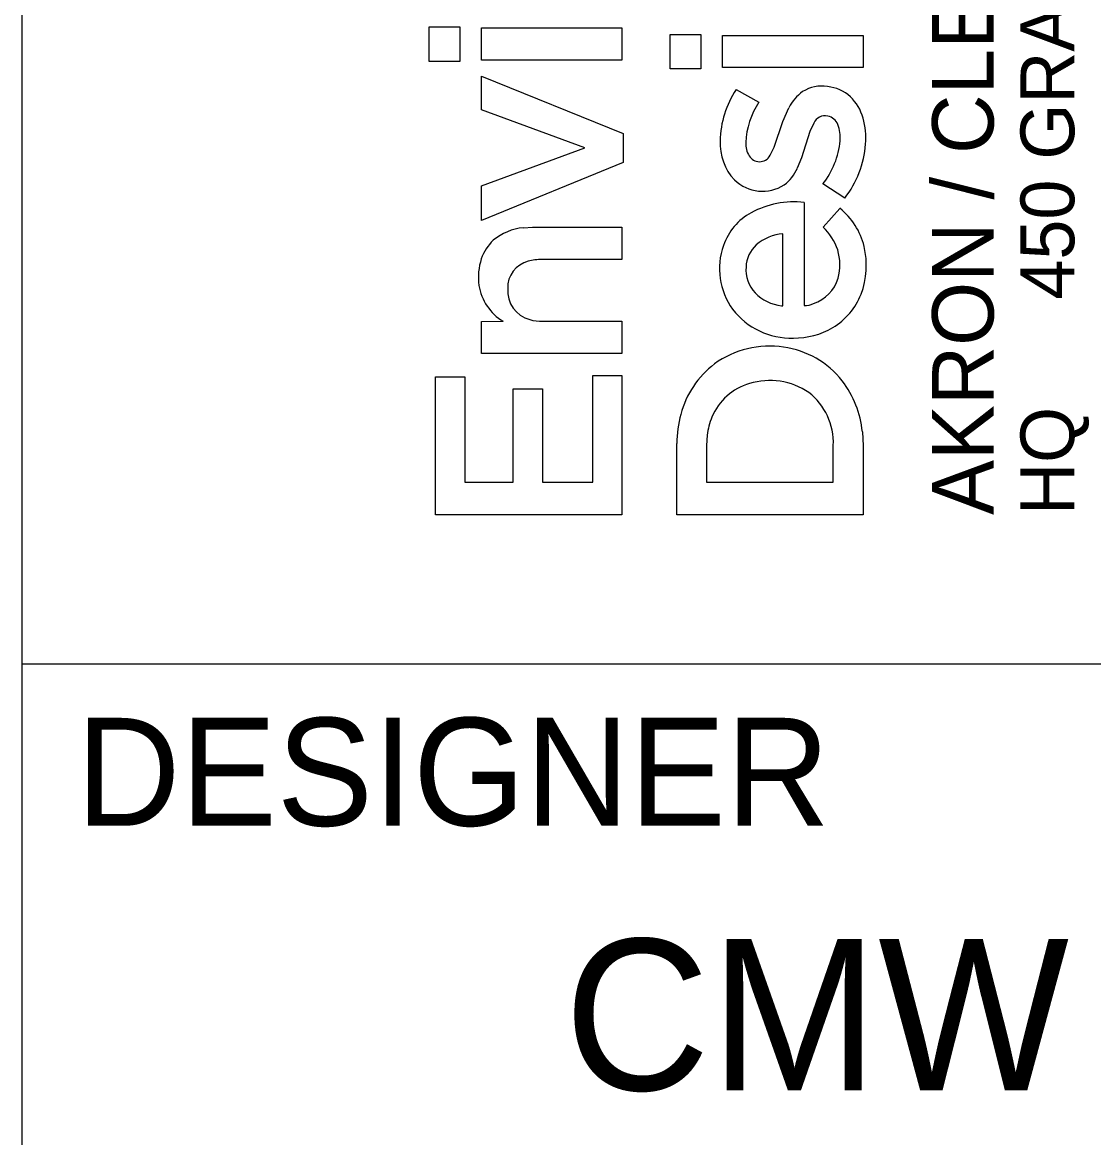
# Model space of a CAD drawing. Extents: x 0 to 1700, y 0 to 1100.
# Drawn here: x 1600 to 1649.6, y 103 to 154.7 of the extents above; entities that cross this region are included whole.
import ezdxf

# ---------------------------------------------------------------- set-up
doc = ezdxf.new("R2010")
doc.units = 0
doc.layers.add('SH_Border', color=7, linetype='Continuous')
doc.layers.add('SH_Data', color=7, linetype='Continuous')

msp = doc.modelspace()

# ---------------------------------------------------------------- linework, layer by layer
at = {"layer": 'SH_Border'}
for p, q in [((1600, 25), (1600, 1075)), ((1600, 125), (1675, 125))]:
    msp.add_line(p, q, dxfattribs=at)
at = {"layer": 'SH_Data'}
for p, q in [((1618.853, 152.909), (1618.853, 154.513)), ((1618.853, 154.513), (1620.272, 154.513)), ((1620.272, 154.513), (1620.272, 152.909)), ((1621.271, 152.971), (1621.271, 154.464)), ((1621.271, 154.464), (1627.786, 154.464)), ((1627.786, 154.464), (1627.786, 152.971)), ((1630.025, 152.555), (1630.025, 154.159)), ((1630.025, 154.159), (1631.444, 154.159)), ((1631.444, 154.159), (1631.444, 152.555)), ((1632.444, 152.617), (1632.444, 154.11)), ((1632.444, 154.11), (1638.958, 154.11)), ((1638.958, 154.11), (1638.958, 152.617)), ((1627.786, 152.971), (1621.271, 152.971)), ((1620.272, 152.909), (1618.853, 152.909)), ((1631.444, 152.555), (1630.025, 152.555)), ((1638.958, 152.617), (1632.444, 152.617)), ((1621.271, 150.663), (1621.271, 152.23)), ((1621.271, 152.23), (1627.835, 149.565)), ((1633.076, 151.603), (1634.134, 151.013)), ((1626.058, 148.899), (1621.271, 150.663)), ((1635.242, 150.129), (1635.518, 150.763)), ((1634.837, 148.934), (1635.242, 150.129)), ((1636.671, 150.05), (1636.492, 149.665)), ((1627.835, 149.565), (1627.835, 148.22)), ((1636.492, 149.665), (1636.106, 148.441)), ((1621.271, 147.147), (1626.058, 148.899)), ((1634.649, 148.558), (1634.837, 148.934)), ((1636.106, 148.441), (1635.911, 147.96)), ((1627.835, 148.22), (1621.271, 145.543)), ((1621.271, 145.543), (1621.271, 147.147)), ((1638.107, 146.571), (1637.099, 147.235)), ((1636.226, 146.373), (1636.232, 141.597)), ((1637.114, 145.232), (1637.884, 146.1)), ((1623.219, 145.199), (1623.645, 145.222)), ((1623.645, 145.222), (1627.785, 145.222)), ((1627.785, 145.222), (1627.786, 143.732)), ((1635.245, 141.591), (1635.245, 144.917)), ((1627.786, 143.732), (1624.07, 143.729)), ((1635.18, 141.583), (1635.245, 141.591)), ((1621.271, 140.864), (1622.276, 140.866)), ((1621.271, 139.373), (1621.271, 140.864)), ((1624.111, 140.866), (1627.785, 140.866)), ((1627.785, 140.866), (1627.786, 139.378)), ((1627.786, 139.378), (1621.271, 139.373)), ((1619.149, 131.896), (1619.149, 138.299)), ((1619.149, 138.299), (1620.506, 138.299)), ((1620.506, 138.299), (1620.506, 133.413)), ((1626.428, 133.413), (1626.428, 138.361)), ((1626.428, 138.361), (1627.786, 138.361)), ((1627.786, 138.361), (1627.786, 131.896)), ((1622.752, 133.413), (1622.752, 137.744)), ((1622.752, 137.744), (1624.109, 137.744)), ((1624.109, 137.744), (1624.109, 133.413)), ((1631.733, 135.589), (1631.703, 135.115)), ((1638.924, 135.748), (1638.958, 135.105)), ((1630.322, 131.899), (1630.322, 135.2)), ((1631.703, 135.115), (1631.703, 133.419)), ((1637.575, 133.417), (1637.576, 135.12)), ((1638.958, 135.105), (1638.958, 131.9)), ((1620.506, 133.413), (1622.752, 133.413)), ((1624.109, 133.413), (1626.428, 133.413)), ((1631.703, 133.419), (1637.575, 133.417)), ((1627.786, 131.896), (1619.149, 131.896)), ((1638.958, 131.9), (1630.322, 131.899))]:
    msp.add_line(p, q, dxfattribs=at)
for points in [[(1618.853, 152.909), (1618.853, 154.513), (1620.272, 154.513), (1620.272, 152.909)], [(1621.271, 152.971), (1621.271, 154.464), (1627.786, 154.464), (1627.786, 152.971)], [(1630.025, 152.555), (1630.025, 154.159), (1631.444, 154.159), (1631.444, 152.555)], [(1632.444, 152.617), (1632.444, 154.11), (1638.958, 154.11), (1638.958, 152.617)], [(1621.271, 145.543), (1621.271, 147.147), (1626.058, 148.899), (1621.271, 150.663), (1621.271, 152.23), (1627.835, 149.565), (1627.835, 148.22)], [(1619.149, 131.896), (1619.149, 138.299), (1620.506, 138.299), (1620.506, 133.413), (1622.752, 133.413), (1622.752, 137.744), (1624.109, 137.744), (1624.109, 133.413), (1626.428, 133.413), (1626.428, 138.361), (1627.786, 138.361), (1627.786, 131.896)]]:
    msp.add_lwpolyline(points, close=True, dxfattribs=at)
for points in [[(1633.076, 151.603), (1634.134, 151.013)], [(1634.649, 148.558), (1634.837, 148.934), (1635.242, 150.129), (1635.518, 150.763)], [(1636.671, 150.05), (1636.492, 149.665), (1636.106, 148.441), (1635.911, 147.96)], [(1638.107, 146.571), (1637.099, 147.235)], [(1636.226, 146.373), (1636.232, 141.597)], [(1637.114, 145.232), (1637.884, 146.1)], [(1623.219, 145.199), (1623.645, 145.222), (1627.785, 145.222), (1627.786, 143.732), (1624.07, 143.729)], [(1635.18, 141.583), (1635.245, 141.591), (1635.245, 144.917)], [(1621.271, 139.373), (1621.271, 140.864), (1622.276, 140.866)], [(1624.111, 140.866), (1627.785, 140.866), (1627.786, 139.378), (1621.271, 139.373)], [(1638.924, 135.748), (1638.958, 135.105), (1638.958, 131.9), (1630.322, 131.899)], [(1631.733, 135.589), (1631.703, 135.115), (1631.703, 133.419), (1637.575, 133.417), (1637.576, 135.12)], [(1630.322, 131.899), (1630.322, 135.2)]]:
    msp.add_lwpolyline(points, dxfattribs=at)
for centre, radius, start, end in [((1636.818, 149.129), 4.486, 146.531, 178.7571), ((1636.818, 149.129), 4.486, 146.531, 178.7571), ((1637.33, 149.856), 2.026, 125.5118, 153.4159), ((1637.33, 149.856), 2.026, 125.5118, 153.4159), ((1637.03, 150.13), 1.632, 80.1719, 122.5197), ((1637.03, 150.13), 1.632, 80.1719, 122.5197), ((1637.139, 149.912), 1.834, 47.7934, 84.6892), ((1637.139, 149.912), 1.834, 47.7934, 84.6892), ((1637.259, 148.945), 3.747, 146.5112, 176.9101), ((1637.259, 148.945), 3.747, 146.5112, 176.9101), ((1636.894, 149.73), 2.134, 14.9966, 46.2063), ((1636.894, 149.73), 2.134, 14.9966, 46.2063), ((1637.192, 149.815), 0.571, 76.6609, 155.7053), ((1637.192, 149.815), 0.571, 76.6609, 155.7053), ((1637.199, 149.756), 0.628, 21.5098, 78.5262), ((1637.199, 149.756), 0.628, 21.5098, 78.5262), ((1636.296, 149.383), 1.605, 354.5726, 22.068), ((1636.296, 149.383), 1.605, 354.5726, 22.068), ((1635.522, 149.337), 3.561, 355.8306, 15.3914), ((1635.522, 149.337), 3.561, 355.8306, 15.3914), ((1634.833, 149.119), 2.503, 177.5366, 222.7932), ((1634.833, 149.119), 2.503, 177.5366, 222.7932), ((1634.655, 149.117), 1.138, 178.4747, 211.0868), ((1634.655, 149.117), 1.138, 178.4747, 211.0868), ((1634.124, 149.575), 3.785, 321.811, 354.7969), ((1634.124, 149.575), 3.785, 321.811, 354.7969), ((1634.476, 149.41), 4.609, 321.9777, 355.8738), ((1634.476, 149.41), 4.609, 321.9777, 355.8738), ((1634.166, 148.835), 0.574, 212.2368, 268.3777), ((1634.166, 148.835), 0.574, 212.2368, 268.3777), ((1634.171, 148.795), 0.534, 267.716, 333.7337), ((1634.171, 148.795), 0.534, 267.716, 333.7337), ((1634.049, 148.79), 2.039, 308.0877, 335.9874), ((1634.049, 148.79), 2.039, 308.0877, 335.9874), ((1634.3, 148.767), 1.875, 225.9854, 302.4797), ((1634.3, 148.767), 1.875, 225.9854, 302.4797), ((1635.76, 142.207), 4.192, 83.615, 118.2876), ((1635.76, 142.207), 4.192, 83.615, 118.2876), ((1635.12, 143.453), 2.792, 118.8308, 160.6244), ((1635.12, 143.453), 2.792, 118.8308, 160.6244), ((1635.872, 143.584), 3.222, 13.5336, 51.3615), ((1635.872, 143.584), 3.222, 13.5336, 51.3615), ((1623.435, 142.714), 2.494, 94.9696, 130.2225), ((1623.435, 142.714), 2.494, 94.9696, 130.2225), ((1635.189, 143.278), 2.743, 19.0357, 45.4406), ((1635.189, 143.278), 2.743, 19.0357, 45.4406), ((1635.393, 142.805), 2.118, 94.008, 130.8817), ((1635.393, 142.805), 2.118, 94.008, 130.8817), ((1623.174, 143.131), 2.008, 132.2219, 161.6818), ((1623.174, 143.131), 2.008, 132.2219, 161.6818), ((1635.521, 143.306), 3.219, 160.5201, 215.7831), ((1635.521, 143.306), 3.219, 160.5201, 215.7831), ((1635.024, 143.314), 1.492, 132.9851, 177.179), ((1635.024, 143.314), 1.492, 132.9851, 177.179), ((1635.535, 143.485), 2.35, 344.6059, 17.007), ((1635.535, 143.485), 2.35, 344.6059, 17.007), ((1635.318, 143.461), 3.79, 339.3542, 13.3785), ((1635.318, 143.461), 3.79, 339.3542, 13.3785), ((1623.936, 142.91), 2.801, 162.2736, 187.7919), ((1623.936, 142.91), 2.801, 162.2736, 187.7919), ((1623.741, 142.433), 1.249, 103.6865, 182.2187), ((1623.741, 142.433), 1.249, 103.6865, 182.2187), ((1624.054, 141.428), 2.301, 89.6049, 105.3284), ((1624.054, 141.428), 2.301, 89.6049, 105.3284), ((1635.085, 143.252), 1.557, 175.0013, 223.283), ((1635.085, 143.252), 1.557, 175.0013, 223.283), ((1636.12, 143.357), 1.752, 288.0077, 343.5508), ((1636.12, 143.357), 1.752, 288.0077, 343.5508), ((1623.513, 142.901), 2.381, 188.962, 238.7037), ((1623.513, 142.901), 2.381, 188.962, 238.7037), ((1623.867, 142.279), 1.378, 175.5854, 255.1439), ((1623.867, 142.279), 1.378, 175.5854, 255.1439), ((1635.446, 143.682), 2.116, 225.0619, 262.7974), ((1635.446, 143.682), 2.116, 225.0619, 262.7974), ((1635.947, 143.26), 3.13, 300.9427, 338.7323), ((1635.947, 143.26), 3.13, 300.9427, 338.7323), ((1636.237, 142.608), 1.01, 269.7003, 294.8711), ((1636.237, 142.608), 1.01, 269.7003, 294.8711), ((1635.626, 143.527), 3.436, 217.7452, 271.6543), ((1635.626, 143.527), 3.436, 217.7452, 271.6543), ((1624.092, 142.974), 2.108, 254.0916, 270.5284), ((1624.092, 142.974), 2.108, 254.0916, 270.5284), ((1635.775, 143.62), 3.528, 269.2048, 300.3341), ((1635.775, 143.62), 3.528, 269.2048, 300.3341), ((1634.614, 135.396), 4.321, 81.194, 125.9984), ((1634.614, 135.396), 4.321, 81.194, 125.9984), ((1634.729, 135.566), 4.136, 37.8521, 82.402), ((1634.729, 135.566), 4.136, 37.8521, 82.402), ((1634.693, 135.446), 4.327, 127.2362, 165.148), ((1634.693, 135.446), 4.327, 127.2362, 165.148), ((1634.447, 135.391), 2.699, 106.1881, 157.3861), ((1634.447, 135.391), 2.699, 106.1881, 157.3861), ((1634.639, 134.931), 3.195, 55.6727, 107.2093), ((1634.639, 134.931), 3.195, 55.6727, 107.2093), ((1634.293, 135.283), 4.654, 5.7333, 37.304), ((1634.293, 135.283), 4.654, 5.7333, 37.304), ((1634.646, 135.249), 2.934, 357.4662, 52.2665), ((1634.646, 135.249), 2.934, 357.4662, 52.2665), ((1635.713, 135.141), 5.391, 164.7861, 179.3704), ((1635.713, 135.141), 5.391, 164.7861, 179.3704), ((1634.914, 135.194), 3.206, 157.3571, 172.9275), ((1634.914, 135.194), 3.206, 157.3571, 172.9275)]:
    msp.add_arc(centre, radius, start, end, dxfattribs=at)

# ---------------------------------------------------------------- texts
for s, height, p in [('450 GRANT ST., AKRON, OH  44311', 2.49231, (1648.744, 141.869)), ('AKRON / CLEVELAND / COLUMBUS', 2.84845, (1645.006, 131.9)), ('HQ ', 2.4923, (1648.744, 131.9))]:
    msp.add_text(s, height=height, rotation=90, dxfattribs=at).set_placement(p)
for s, height, p in [('DESIGNER', 5, (1602.5, 117.5)), ('CMW', 7, (1625.104, 105.25))]:
    msp.add_text(s, height=height, dxfattribs=at).set_placement(p)

doc.saveas('drawing.dxf')
